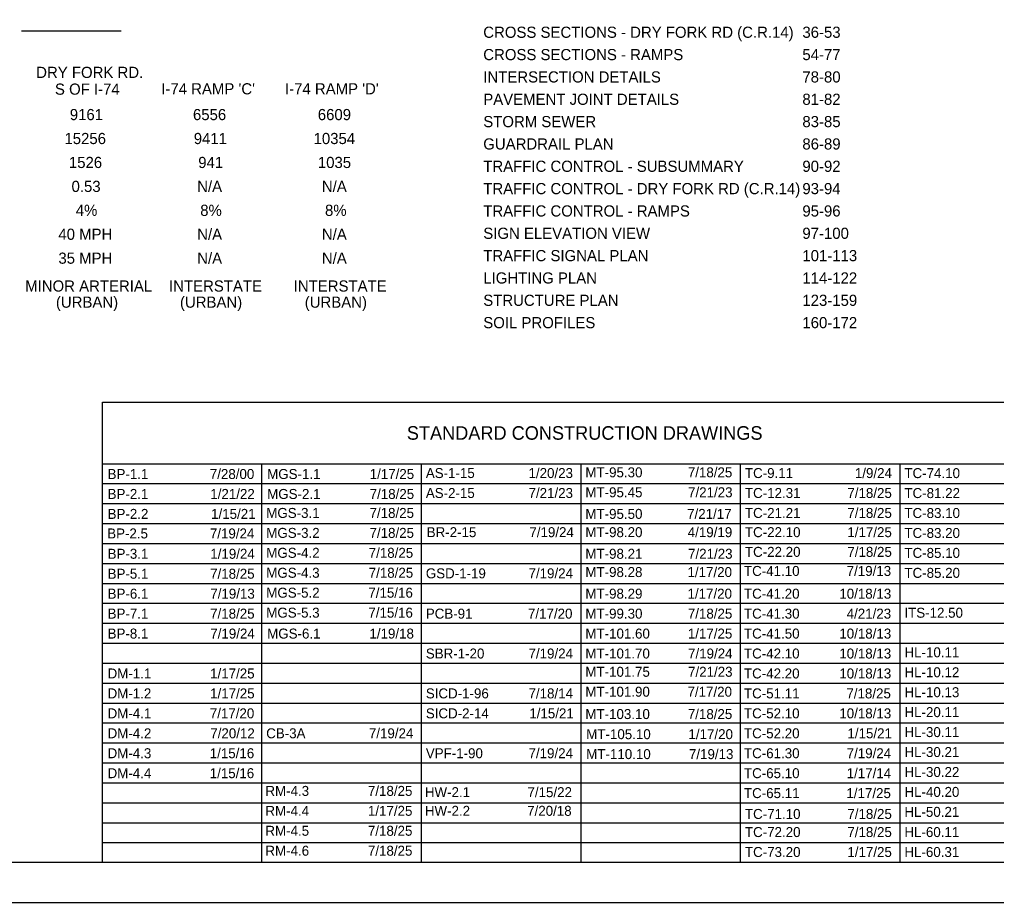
# Model space of a CAD drawing. Extents: x -7.5 to 26.5, y 3.5 to 25.5.
# Drawn here: x 0.27 to 12.51, y 3.5 to 14.57 of the extents above; entities that cross this region are included whole.
import ezdxf

# ---------------------------------------------------------------- set-up
doc = ezdxf.new("R2010")
doc.units = 0
for name, color, linetype in [('SH_Border', 7, 'Continuous'), ('SH_Cut_Line', 7, 'Continuous'), ('SH_Data', 7, 'Continuous'), ('SH_Text', 7, 'Continuous')]:
    doc.layers.add(name, color=color, linetype=linetype)

msp = doc.modelspace()

# ---------------------------------------------------------------- linework, layer by layer
at = {"layer": 'SH_Border'}
msp.add_lwpolyline([(-5.957, 25), (26.043, 25), (26.043, 4), (-5.957, 4)], close=True, dxfattribs=at)
at = {"layer": 'SH_Cut_Line'}
msp.add_lwpolyline([(-7.457, 3.5), (26.543, 3.5), (26.543, 25.5), (-7.457, 25.5)], close=True, dxfattribs=at)
at = {"layer": 'SH_Data'}
for p, q in [((1.543, 14.422), (0.293, 14.422)), ((1.306, 9.771), (16.756, 9.771)), ((1.306, 4), (1.306, 9.771)), ((1.306, 9), (16.756, 9)), ((3.306, 4), (3.306, 9)), ((5.306, 4), (5.306, 9)), ((7.306, 4), (7.306, 9)), ((9.306, 4), (9.306, 9)), ((11.306, 4), (11.306, 9)), ((1.306, 8.75), (16.756, 8.75)), ((1.306, 8.5), (16.756, 8.5)), ((1.306, 8.25), (16.756, 8.25)), ((1.306, 8), (16.756, 8)), ((1.306, 7.75), (16.756, 7.75)), ((1.306, 7.5), (16.756, 7.5)), ((1.306, 7.25), (16.756, 7.25)), ((1.306, 7), (16.756, 7)), ((1.306, 6.75), (16.756, 6.75)), ((1.306, 6.5), (16.756, 6.5)), ((1.306, 6.25), (16.756, 6.25)), ((1.306, 6), (16.756, 6)), ((1.306, 5.75), (16.756, 5.75)), ((1.306, 5.5), (16.756, 5.5)), ((1.306, 5.25), (16.756, 5.25)), ((1.306, 5), (16.756, 5)), ((1.306, 4.75), (16.756, 4.75)), ((1.306, 4.5), (16.756, 4.5)), ((1.306, 4.25), (16.756, 4.25))]:
    msp.add_line(p, q, dxfattribs=at)

# ---------------------------------------------------------------- texts
at = {"layer": 'SH_Text'}
for s, height, p in [('CROSS SECTIONS - DRY FORK RD (C.R.14)', 0.14, (6.081, 14.338)), ('36-53', 0.14, (10.081, 14.338)), ('CROSS SECTIONS - RAMPS', 0.14, (6.081, 14.058)), ('54-77', 0.14, (10.081, 14.058)), ('DRY FORK RD.', 0.14, (0.477, 13.835)), ('INTERSECTION DETAILS', 0.14, (6.081, 13.778)), ('78-80', 0.14, (10.081, 13.778)), ('S OF I-74', 0.14, (0.712, 13.625)), ("I-74 RAMP 'C'", 0.14, (2.045, 13.629)), ("I-74 RAMP 'D'", 0.14, (3.596, 13.629)), ('PAVEMENT JOINT DETAILS', 0.14, (6.081, 13.498)), ('81-82', 0.14, (10.081, 13.498)), ('9161', 0.14, (0.898, 13.306)), ('6556', 0.14, (2.442, 13.306)), ('6609', 0.14, (4.007, 13.306)), ('STORM SEWER', 0.14, (6.081, 13.218)), ('83-85', 0.14, (10.081, 13.218)), ('15256', 0.14, (0.831, 13.006)), ('9411', 0.14, (2.452, 13.006)), ('10354', 0.14, (3.954, 13.006)), ('GUARDRAIL PLAN', 0.14, (6.081, 12.938)), ('86-89', 0.14, (10.081, 12.938)), ('1526', 0.14, (0.887, 12.706)), ('941', 0.14, (2.508, 12.706)), ('1035', 0.14, (4.008, 12.706)), ('TRAFFIC CONTROL - SUBSUMMARY', 0.14, (6.081, 12.658)), ('90-92', 0.14, (10.081, 12.658)), ('0.53', 0.14, (0.92, 12.406)), ('N/A', 0.14, (2.495, 12.406)), ('N/A', 0.14, (4.058, 12.406)), ('TRAFFIC CONTROL - DRY FORK RD (C.R.14) ', 0.14, (6.081, 12.378)), ('93-94', 0.14, (10.081, 12.378)), ('4%', 0.14, (0.973, 12.106)), ('8%', 0.14, (2.533, 12.106)), ('8%', 0.14, (4.097, 12.106)), ('TRAFFIC CONTROL - RAMPS', 0.14, (6.081, 12.098)), ('95-96', 0.14, (10.081, 12.098)), ('40 MPH', 0.14, (0.755, 11.806)), ('N/A', 0.14, (2.495, 11.806)), ('N/A', 0.14, (4.058, 11.806)), ('SIGN ELEVATION VIEW', 0.14, (6.081, 11.818)), ('97-100', 0.14, (10.081, 11.818)), ('35 MPH', 0.14, (0.755, 11.506)), ('N/A', 0.14, (2.495, 11.506)), ('N/A', 0.14, (4.058, 11.506)), ('TRAFFIC SIGNAL PLAN', 0.14, (6.081, 11.538)), ('101-113', 0.14, (10.081, 11.538)), ('LIGHTING PLAN', 0.14, (6.081, 11.258)), ('114-122', 0.14, (10.081, 11.258)), ('MINOR ARTERIAL', 0.14, (0.339, 11.157)), ('INTERSTATE', 0.14, (2.142, 11.157)), ('INTERSTATE', 0.14, (3.705, 11.157)), ('(URBAN)', 0.14, (0.724, 10.955)), ('(URBAN)', 0.14, (2.279, 10.955)), ('(URBAN)', 0.14, (3.843, 10.955)), ('STRUCTURE PLAN', 0.14, (6.081, 10.978)), ('123-159', 0.14, (10.081, 10.978)), ('SOIL PROFILES', 0.14, (6.081, 10.698)), ('160-172', 0.14, (10.081, 10.698)), ('STANDARD CONSTRUCTION DRAWINGS', 0.17, (5.123, 9.3)), ('7/28/00', 0.125, (2.653, 8.808)), ('1/17/25', 0.125, (4.657, 8.808)), ('AS-1-15', 0.125, (5.361, 8.82)), ('1/20/23', 0.125, (6.648, 8.82)), ('MT-95.30', 0.125, (7.361, 8.829)), ('7/18/25', 0.125, (8.645, 8.829)), ('TC-9.11', 0.125, (9.361, 8.82)), ('1/9/24', 0.125, (10.739, 8.82)), ('TC-74.10', 0.125, (11.36, 8.819)), ('BP-1.1', 0.125, (1.372, 8.808)), ('MGS-1.1', 0.125, (3.372, 8.808)), ('AS-2-15', 0.125, (5.361, 8.57)), ('7/21/23', 0.125, (6.648, 8.57)), ('MT-95.45', 0.125, (7.361, 8.579)), ('7/21/23', 0.125, (8.648, 8.579)), ('TC-12.31', 0.125, (9.361, 8.57)), ('7/18/25', 0.125, (10.645, 8.57)), ('TC-81.22', 0.125, (11.36, 8.569)), ('BP-2.1', 0.125, (1.372, 8.558)), ('1/21/22', 0.125, (2.659, 8.558)), ('MGS-2.1', 0.125, (3.372, 8.558)), ('7/18/25', 0.125, (4.657, 8.558)), ('7/18/25', 0.125, (4.655, 8.32)), ('7/18/25', 0.125, (10.645, 8.32)), ('BP-2.2', 0.125, (1.372, 8.308)), ('1/15/21', 0.125, (2.669, 8.308)), ('MGS-3.1', 0.125, (3.361, 8.32)), ('MT-95.50', 0.125, (7.361, 8.308)), ('7/21/17', 0.125, (8.636, 8.308)), ('TC-21.21', 0.125, (9.361, 8.32)), ('TC-83.10', 0.125, (11.36, 8.319)), ('BR-2-15', 0.125, (5.372, 8.079)), ('7/19/24', 0.125, (6.659, 8.079)), ('MT-98.20', 0.125, (7.361, 8.079)), ('4/19/19', 0.125, (8.644, 8.079)), ('TC-22.10', 0.125, (9.361, 8.079)), ('1/17/25', 0.125, (10.645, 8.079)), ('BP-2.5', 0.125, (1.367, 8.063)), ('7/19/24', 0.125, (2.654, 8.063)), ('MGS-3.2', 0.125, (3.361, 8.07)), ('7/18/25', 0.125, (4.655, 8.07)), ('TC-83.20', 0.125, (11.36, 8.069)), ('7/18/25', 0.125, (10.645, 7.832)), ('BP-3.1', 0.125, (1.372, 7.808)), ('1/19/24', 0.125, (2.659, 7.808)), ('MGS-4.2', 0.125, (3.361, 7.82)), ('7/18/25', 0.125, (4.645, 7.82)), ('MT-98.21', 0.125, (7.361, 7.808)), ('7/21/23', 0.125, (8.648, 7.808)), ('TC-22.20', 0.125, (9.361, 7.832)), ('TC-85.10', 0.125, (11.36, 7.819)), ('TC-41.10', 0.125, (9.349, 7.593)), ('7/19/13', 0.125, (10.636, 7.593)), ('BP-5.1', 0.125, (1.372, 7.558)), ('7/18/25', 0.125, (2.657, 7.558)), ('MGS-4.3', 0.125, (3.361, 7.57)), ('7/18/25', 0.125, (4.645, 7.57)), ('GSD-1-19', 0.125, (5.361, 7.563)), ('7/19/24', 0.125, (6.648, 7.563)), ('MT-98.28', 0.125, (7.361, 7.579)), ('1/17/20', 0.125, (8.641, 7.579)), ('TC-85.20', 0.125, (11.36, 7.569)), ('BP-6.1', 0.125, (1.372, 7.308)), ('7/19/13', 0.125, (2.659, 7.308)), ('MGS-5.2', 0.125, (3.361, 7.32)), ('7/15/16', 0.125, (4.641, 7.32)), ('MT-98.29', 0.125, (7.361, 7.308)), ('1/17/20', 0.125, (8.641, 7.308)), ('TC-41.20', 0.125, (9.349, 7.308)), ('10/18/13', 0.125, (10.544, 7.308)), ('BP-7.1', 0.125, (1.372, 7.058)), ('7/18/25', 0.125, (2.657, 7.058)), ('MGS-5.3', 0.125, (3.361, 7.07)), ('7/15/16', 0.125, (4.641, 7.07)), ('PCB-91', 0.125, (5.361, 7.058)), ('7/17/20', 0.125, (6.641, 7.058)), ('MT-99.30', 0.125, (7.361, 7.058)), ('7/18/25', 0.125, (8.645, 7.058)), ('TC-41.30', 0.125, (9.349, 7.058)), ('4/21/23', 0.125, (10.636, 7.058)), ('ITS-12.50', 0.125, (11.36, 7.069)), ('BP-8.1', 0.125, (1.372, 6.808)), ('7/19/24', 0.125, (2.659, 6.808)), ('MGS-6.1', 0.125, (3.372, 6.808)), ('1/19/18', 0.125, (4.654, 6.808)), ('MT-101.60', 0.125, (7.361, 6.808)), ('1/17/25', 0.125, (8.645, 6.808)), ('TC-41.50', 0.125, (9.349, 6.808)), ('10/18/13', 0.125, (10.544, 6.808)), ('SBR-1-20', 0.125, (5.361, 6.558)), ('7/19/24', 0.125, (6.648, 6.558)), ('MT-101.70', 0.125, (7.361, 6.558)), ('7/19/24', 0.125, (8.648, 6.558)), ('TC-42.10', 0.125, (9.349, 6.558)), ('10/18/13', 0.125, (10.544, 6.558)), ('HL-10.11', 0.125, (11.361, 6.573)), ('DM-1.1', 0.125, (1.372, 6.308)), ('1/17/25', 0.125, (2.657, 6.308)), ('MT-101.75', 0.125, (7.361, 6.329)), ('7/21/23', 0.125, (8.648, 6.329)), ('TC-42.20', 0.125, (9.349, 6.308)), ('10/18/13', 0.125, (10.544, 6.308)), ('HL-10.12', 0.125, (11.361, 6.323)), ('DM-1.2', 0.125, (1.372, 6.058)), ('1/17/25', 0.125, (2.657, 6.058)), ('SICD-1-96', 0.125, (5.361, 6.058)), ('7/18/14', 0.125, (6.648, 6.058)), ('MT-101.90', 0.125, (7.361, 6.079)), ('7/17/20', 0.125, (8.641, 6.079)), ('TC-51.11', 0.125, (9.349, 6.058)), ('7/18/25', 0.125, (10.633, 6.058)), ('HL-10.13', 0.125, (11.361, 6.073)), ('DM-4.1', 0.125, (1.372, 5.808)), ('7/17/20', 0.125, (2.653, 5.808)), ('SICD-2-14', 0.125, (5.361, 5.808)), ('1/15/21', 0.125, (6.658, 5.808)), ('MT-103.10', 0.125, (7.361, 5.799)), ('7/18/25', 0.125, (8.645, 5.799)), ('TC-52.10', 0.125, (9.349, 5.808)), ('10/18/13', 0.125, (10.544, 5.808)), ('HL-20.11', 0.125, (11.361, 5.823)), ('DM-4.2', 0.125, (1.372, 5.558)), ('7/20/12', 0.125, (2.659, 5.558)), ('CB-3A', 0.125, (3.36, 5.558)), ('7/19/24', 0.125, (4.647, 5.558)), ('MT-105.10', 0.125, (7.372, 5.547)), ('1/17/20', 0.125, (8.653, 5.547)), ('TC-52.20', 0.125, (9.349, 5.558)), ('1/15/21', 0.125, (10.646, 5.558)), ('HL-30.11', 0.125, (11.361, 5.573)), ('DM-4.3', 0.125, (1.372, 5.308)), ('1/15/16', 0.125, (2.652, 5.308)), ('VPF-1-90', 0.125, (5.361, 5.308)), ('7/19/24', 0.125, (6.648, 5.308)), ('MT-110.10', 0.125, (7.372, 5.297)), ('7/19/13', 0.125, (8.659, 5.297)), ('TC-61.30', 0.125, (9.349, 5.308)), ('7/19/24', 0.125, (10.636, 5.308)), ('HL-30.21', 0.125, (11.361, 5.323)), ('DM-4.4', 0.125, (1.372, 5.058)), ('1/15/16', 0.125, (2.652, 5.058)), ('TC-65.10', 0.125, (9.349, 5.058)), ('1/17/14', 0.125, (10.636, 5.058)), ('HL-30.22', 0.125, (11.361, 5.073)), ('RM-4.3', 0.125, (3.35, 4.836)), ('7/18/25', 0.125, (4.635, 4.836)), ('HW-2.1', 0.125, (5.349, 4.82)), ('7/15/22', 0.125, (6.635, 4.82)), ('TC-65.11', 0.125, (9.349, 4.808)), ('1/17/25', 0.125, (10.633, 4.808)), ('HL-40.20', 0.125, (11.361, 4.823)), ('RM-4.4', 0.125, (3.35, 4.586)), ('1/17/25', 0.125, (4.635, 4.586)), ('HW-2.2', 0.125, (5.349, 4.586)), ('7/20/18', 0.125, (6.631, 4.586)), ('TC-71.10', 0.125, (9.361, 4.547)), ('7/18/25', 0.125, (10.645, 4.547)), ('HL-50.21', 0.125, (11.36, 4.573)), ('RM-4.5', 0.125, (3.35, 4.336)), ('7/18/25', 0.125, (4.635, 4.336)), ('TC-72.20', 0.125, (9.361, 4.32)), ('7/18/25', 0.125, (10.645, 4.32)), ('HL-60.11', 0.125, (11.36, 4.32)), ('RM-4.6', 0.125, (3.35, 4.086)), ('7/18/25', 0.125, (4.635, 4.086)), ('TC-73.20', 0.125, (9.361, 4.07)), ('1/17/25', 0.125, (10.645, 4.07)), ('HL-60.31', 0.125, (11.36, 4.07))]:
    msp.add_text(s, height=height, dxfattribs=at).set_placement(p)

doc.saveas('drawing.dxf')
